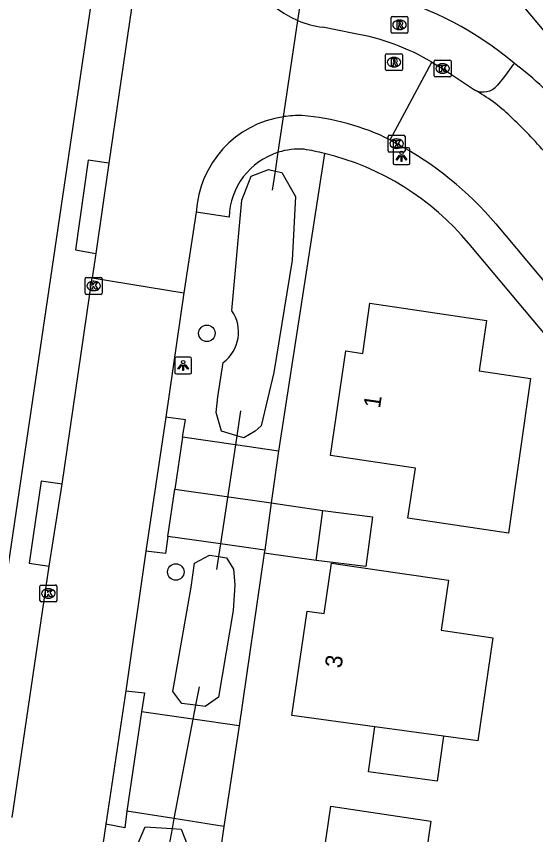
# Model space of a CAD drawing. Extents: x 164150 to 165261, y 382513 to 383432.
# Drawn here: x 164667.2 to 164697.92, y 383094.82 to 383143.23 of the extents above; entities that cross this region are included whole.
import ezdxf

# ---------------------------------------------------------------- set-up
doc = ezdxf.new("R2010")
doc.units = 0
for name, color, linetype in [('IMGEO_Boom', 7, 'Continuous'), ('IMGEO_Duiker', 7, 'Continuous'), ('IMGEO_Greppel_droge_sloot', 7, 'Continuous'), ('IMGEO_Groenvoorziening', 7, 'Continuous'), ('IMGEO_Kolk', 7, 'Continuous'), ('IMGEO_Lichtpunt', 7, 'Continuous'), ('IMGEO_Pand', 7, 'Continuous'), ('IMGEO_Pand_nummerreeks', 7, 'Continuous'), ('IMGEO_Rijbaan_lokaal_open', 7, 'Continuous'), ('IMGEO_Rioolput', 7, 'Continuous'), ('IMGEO_Voetpad_open', 7, 'Continuous')]:
    doc.layers.add(name, color=color, linetype=linetype)

msp = doc.modelspace()

# ---------------------------------------------------------------- linework, layer by layer
at = {"layer": 'IMGEO_Boom'}
for centre in [(164678.467, 383124.48), (164676.627, 383110.359)]:
    msp.add_circle(centre, 0.489, dxfattribs=at)
at = {"layer": 'IMGEO_Duiker'}
for points in [[(164682.359, 383132.944), (164682.528, 383134.079), (164682.693, 383135.192), (164683.006, 383137.299), (164683.852, 383142.989), (164684.274, 383145.824), (164684.646, 383148.329), (164684.685, 383148.589)], [(164680.465, 383119.904), (164680.238, 383118.413), (164680.158, 383117.886), (164679.265, 383112.022), (164679.151, 383111.27), (164679.035, 383110.511)], [(164678.002, 383103.555), (164677.798, 383102.481), (164677.639, 383101.645), (164676.521, 383095.769), (164676.409, 383095.178), (164676.228, 383094.227)]]:
    msp.add_lwpolyline(points, dxfattribs=at)
at = {"layer": 'IMGEO_Greppel_droge_sloot'}
for points in [[(164679.948, 383125.821), (164680.545, 383132.357), (164681.079, 383133.781), (164682.112, 383134.173), (164682.528, 383134.079), (164682.895, 383133.995), (164683.711, 383132.584)], [(164683.711, 383132.584), (164683.514, 383128.812), (164682.437, 383122.17), (164681.688, 383119.003), (164681.328, 383118.682), (164680.652, 383118.29), (164680.238, 383118.413), (164679.334, 383118.682), (164679.014, 383119.786), (164679.122, 383120.729), (164679.428, 383122.76)], [(164677.531, 383109.471), (164677.731, 383110.883), (164678.622, 383111.346), (164679.151, 383111.27), (164679.619, 383111.203), (164680.046, 383110.526), (164680.118, 383109.601), (164680.019, 383108.086), (164679.153, 383102.95), (164678.372, 383102.407), (164677.798, 383102.481), (164676.984, 383102.585), (164676.449, 383103.297), (164677.531, 383109.471)], [(164672.986, 383084.821), (164673.965, 383093.315), (164674.811, 383095.284), (164676.409, 383095.178), (164676.948, 383095.142), (164677.626, 383093.43), (164676.313, 383084.457), (164675.666, 383082.856), (164674.482, 383083.009), (164673.707, 383083.11)]]:
    msp.add_lwpolyline(points, dxfattribs=at)
msp.add_arc((164678.112, 383124.558), 2.228, 306.1933, 34.5241, dxfattribs=at)
at = {"layer": 'IMGEO_Groenvoorziening'}
for points in [[(164685.42, 383135.126), (164682.705, 383117.517)], [(164681.864, 383111.47), (164680.372, 383101.254)], [(164679.477, 383095.307), (164679.334, 383094.335)]]:
    msp.add_lwpolyline(points, dxfattribs=at)
at = {"layer": 'IMGEO_Kolk'}
for p, q in [((164691.91, 383139.721), (164691.91, 383140.573)), ((164691.985, 383140.647), (164692.837, 383140.647)), ((164692.911, 383140.573), (164692.911, 383139.721)), ((164692.398, 383140.427), (164692.423, 383140.427)), ((164692.837, 383139.647), (164691.985, 383139.647)), ((164692.421, 383139.867), (164692.396, 383139.867)), ((164689.263, 383136.204), (164690.115, 383136.204)), ((164689.188, 383135.278), (164689.188, 383136.13)), ((164689.676, 383135.984), (164689.701, 383135.984)), ((164690.189, 383136.13), (164690.189, 383135.278)), ((164689.699, 383135.424), (164689.674, 383135.424)), ((164690.115, 383135.204), (164689.263, 383135.204)), ((164671.267, 383126.859), (164671.267, 383127.711)), ((164671.342, 383127.785), (164672.194, 383127.785)), ((164671.755, 383127.565), (164671.78, 383127.565)), ((164672.268, 383127.711), (164672.268, 383126.859)), ((164671.778, 383127.005), (164671.753, 383127.005)), ((164672.194, 383126.785), (164671.342, 383126.785)), ((164668.669, 383109.589), (164669.521, 383109.589)), ((164668.594, 383108.663), (164668.594, 383109.515)), ((164669.082, 383109.369), (164669.107, 383109.369)), ((164669.595, 383109.515), (164669.595, 383108.663)), ((164669.521, 383108.589), (164668.669, 383108.589)), ((164669.105, 383108.809), (164669.08, 383108.809))]:
    msp.add_line(p, q, dxfattribs=at)
for points in [[(164691.91, 383139.721), (164691.91, 383140.573)], [(164691.985, 383140.647), (164692.837, 383140.647)], [(164692.911, 383140.573), (164692.911, 383139.721)], [(164692.231, 383140.347), (164692.354, 383140.347), (164692.354, 383140.196), (164692.484, 383140.347), (164692.648, 383140.347), (164692.502, 383140.196), (164692.655, 383139.947), (164692.503, 383139.947), (164692.418, 383140.111), (164692.354, 383140.044), (164692.354, 383139.947), (164692.231, 383139.947), (164692.231, 383140.347)], [(164692.837, 383139.647), (164691.985, 383139.647)], [(164689.263, 383136.204), (164690.115, 383136.204)], [(164689.188, 383135.278), (164689.188, 383136.13)], [(164689.509, 383135.904), (164689.632, 383135.904), (164689.632, 383135.753), (164689.762, 383135.904), (164689.926, 383135.904), (164689.78, 383135.753), (164689.933, 383135.504), (164689.781, 383135.504), (164689.696, 383135.668), (164689.632, 383135.601), (164689.632, 383135.504), (164689.509, 383135.504), (164689.509, 383135.904)], [(164690.189, 383136.13), (164690.189, 383135.278)], [(164690.115, 383135.204), (164689.263, 383135.204)], [(164671.267, 383126.859), (164671.267, 383127.711)], [(164671.342, 383127.785), (164672.194, 383127.785)], [(164671.588, 383127.485), (164671.711, 383127.485), (164671.711, 383127.334), (164671.841, 383127.485), (164672.005, 383127.485), (164671.859, 383127.334), (164672.012, 383127.085), (164671.86, 383127.085), (164671.775, 383127.249), (164671.711, 383127.182), (164671.711, 383127.085), (164671.588, 383127.085), (164671.588, 383127.485)], [(164672.268, 383127.711), (164672.268, 383126.859)], [(164672.194, 383126.785), (164671.342, 383126.785)], [(164668.669, 383109.589), (164669.521, 383109.589)], [(164668.594, 383108.663), (164668.594, 383109.515)], [(164668.915, 383109.289), (164669.038, 383109.289), (164669.038, 383109.138), (164669.168, 383109.289), (164669.332, 383109.289), (164669.186, 383109.138), (164669.339, 383108.889), (164669.187, 383108.889), (164669.102, 383109.053), (164669.038, 383108.986), (164669.038, 383108.889), (164668.915, 383108.889), (164668.915, 383109.289)], [(164669.595, 383109.515), (164669.595, 383108.663)], [(164669.521, 383108.589), (164668.669, 383108.589)]]:
    msp.add_lwpolyline(points, dxfattribs=at)
for centre, start, end in [((164691.987, 383140.571), 91.552, 178.448), ((164691.987, 383140.571), 91.552, 178.448), ((164692.835, 383140.571), 1.552, 88.448), ((164692.835, 383140.571), 1.552, 88.448), ((164691.987, 383139.723), 181.552, 268.448), ((164691.987, 383139.723), 181.552, 268.448), ((164692.835, 383139.723), 271.552, 358.448), ((164692.835, 383139.723), 271.552, 358.448), ((164689.265, 383136.128), 91.552, 178.448), ((164689.265, 383136.128), 91.552, 178.448), ((164690.113, 383136.128), 1.552, 88.448), ((164690.113, 383136.128), 1.552, 88.448), ((164689.265, 383135.28), 181.552, 268.448), ((164689.265, 383135.28), 181.552, 268.448), ((164690.113, 383135.28), 271.552, 358.448), ((164690.113, 383135.28), 271.552, 358.448), ((164671.344, 383127.709), 91.552, 178.448), ((164671.344, 383127.709), 91.552, 178.448), ((164672.192, 383127.709), 1.552, 88.448), ((164672.192, 383127.709), 1.552, 88.448), ((164671.344, 383126.861), 181.552, 268.448), ((164671.344, 383126.861), 181.552, 268.448), ((164672.192, 383126.861), 271.552, 358.448), ((164672.192, 383126.861), 271.552, 358.448), ((164668.671, 383109.513), 91.552, 178.448), ((164668.671, 383109.513), 91.552, 178.448), ((164669.519, 383109.513), 1.552, 88.448), ((164669.519, 383109.513), 1.552, 88.448), ((164668.671, 383108.665), 181.552, 268.448), ((164668.671, 383108.665), 181.552, 268.448), ((164669.519, 383108.665), 271.552, 358.448), ((164669.519, 383108.665), 271.552, 358.448)]:
    msp.add_arc(centre, 0.0765, start, end, dxfattribs=at)
for centre, major_axis, ratio, start_param, end_param in [((164692.397, 383140.147), (-0.387, 0.002), 0.722429, 4.712389, 7.853982), ((164692.422, 383140.147), (-0.39, 0.002), 0.717154, 1.570796, 4.712389), ((164689.675, 383135.704), (-0.387, 0.002), 0.722429, 4.712389, 7.853982), ((164689.7, 383135.704), (-0.39, 0.002), 0.717154, 1.570796, 4.712389), ((164671.754, 383127.285), (-0.387, 0.002), 0.722429, 4.712389, 7.853982), ((164671.779, 383127.285), (-0.39, 0.002), 0.717154, 1.570796, 4.712389), ((164669.081, 383109.089), (-0.387, 0.002), 0.722429, 4.712389, 7.853982), ((164669.106, 383109.089), (-0.39, 0.002), 0.717154, 1.570796, 4.712389)]:
    msp.add_ellipse(centre, major_axis=major_axis, ratio=ratio, start_param=start_param, end_param=end_param, dxfattribs=at)
at = {"layer": 'IMGEO_Lichtpunt'}
for p, q in [((164689.483, 383135.361), (164689.483, 383134.554)), ((164689.483, 383135.361), (164689.483, 383134.554)), ((164690.385, 383135.456), (164689.577, 383135.456)), ((164690.385, 383135.456), (164689.577, 383135.456)), ((164690.479, 383134.554), (164690.479, 383135.361)), ((164690.479, 383134.554), (164690.479, 383135.361)), ((164689.577, 383134.46), (164690.385, 383134.46)), ((164689.577, 383134.46), (164690.385, 383134.46)), ((164676.567, 383122.979), (164676.567, 383122.172)), ((164676.567, 383122.979), (164676.567, 383122.172)), ((164677.469, 383123.074), (164676.661, 383123.074)), ((164677.469, 383123.074), (164676.661, 383123.074)), ((164677.563, 383122.172), (164677.563, 383122.979)), ((164677.563, 383122.172), (164677.563, 383122.979)), ((164676.661, 383122.078), (164677.469, 383122.078)), ((164676.661, 383122.078), (164677.469, 383122.078))]:
    msp.add_line(p, q, dxfattribs=at)
for points in [[(164689.857, 383135.025), (164689.896, 383134.997), (164689.708, 383134.735), (164689.67, 383134.762), (164689.857, 383135.025)], [(164689.959, 383134.977), (164690.006, 383134.977), (164690.006, 383134.655), (164689.959, 383134.655), (164689.959, 383134.977)], [(164690.069, 383134.997), (164690.107, 383135.024), (164690.294, 383134.762), (164690.255, 383134.734), (164690.069, 383134.997)], [(164676.941, 383122.643), (164676.98, 383122.615), (164676.792, 383122.353), (164676.754, 383122.38), (164676.941, 383122.643)], [(164677.153, 383122.615), (164677.191, 383122.642), (164677.378, 383122.38), (164677.339, 383122.352), (164677.153, 383122.615)], [(164677.043, 383122.595), (164677.09, 383122.595), (164677.09, 383122.273), (164677.043, 383122.273), (164677.043, 383122.595)]]:
    msp.add_lwpolyline(points, dxfattribs=at)
for centre in [(164689.982, 383135.159), (164677.066, 383122.777)]:
    msp.add_circle(centre, 0.0994, dxfattribs=at)
for centre, start, end in [((164689.577, 383135.361), 90, 180), ((164689.577, 383135.361), 90, 180), ((164690.385, 383135.361), 0, 90), ((164690.385, 383135.361), 0, 90), ((164689.577, 383134.554), 180, 270), ((164689.577, 383134.554), 180, 270), ((164690.385, 383134.554), 270, 0), ((164690.385, 383134.554), 270, 360), ((164676.661, 383122.979), 90, 180), ((164676.661, 383122.979), 90, 180), ((164677.469, 383122.979), 0, 90), ((164677.469, 383122.979), 0, 90), ((164676.661, 383122.172), 180, 270), ((164676.661, 383122.172), 180, 270), ((164677.469, 383122.172), 270, 0), ((164677.469, 383122.172), 270, 360)]:
    msp.add_arc(centre, 0.0946, start, end, dxfattribs=at)
at = {"layer": 'IMGEO_Pand'}
for points in [[(164695.223, 383146.183), (164698.886, 383141.788), (164700.592, 383143.214), (164702.499, 383140.933), (164709.288, 383146.608), (164703.728, 383153.266)], [(164696.304, 383112.656), (164690.359, 383113.537), (164690.799, 383116.508), (164685.777, 383117.252), (164686.683, 383123.435), (164687.684, 383123.28), (164688.111, 383126.26), (164695.018, 383125.233), (164694.576, 383122.259), (164697.618, 383121.807), (164696.304, 383112.656)], [(164685.334, 383113.998), (164688.257, 383113.615), (164687.868, 383110.687), (164684.941, 383111.045)], [(164684.941, 383111.045), (164685.334, 383113.998)], [(164688.395, 383101.199), (164683.491, 383101.872), (164684.404, 383108.045), (164685.4, 383107.912), (164685.832, 383110.885), (164689.611, 383110.336), (164692.759, 383109.878), (164692.328, 383106.91), (164695.381, 383106.466), (164694.494, 383100.363), (164692.457, 383100.642)], [(164692.457, 383100.642), (164692.092, 383097.977), (164688.03, 383098.534), (164688.395, 383101.199)], [(164692.457, 383100.642), (164688.395, 383101.199)], [(164681.443, 383088.028), (164681.531, 383088.632), (164680.878, 383088.728), (164681.278, 383091.454), (164681.931, 383091.358), (164682.314, 383093.967), (164685.361, 383093.531), (164685.804, 383096.496), (164691.724, 383095.61), (164691.218, 383092.228), (164690.728, 383092.301), (164689.907, 383086.771)]]:
    msp.add_lwpolyline(points, dxfattribs=at)
at = {"layer": 'IMGEO_Rijbaan_lokaal_open'}
for points in [[(164675.111, 383151.432), (164675.108, 383151.287), (164672.668, 383134.547)], [(164687.154, 383142.219), (164685.328, 383142.586)], [(164689.308, 383135.927), (164691.776, 383140.523)], [(164691.776, 383140.523), (164692.411, 383140.147), (164694.29, 383138.89)], [(164689.308, 383135.927), (164689.689, 383135.704)], [(164672.668, 383134.547), (164671.889, 383129.204)], [(164677.839, 383131.639), (164677.103, 383126.885)], [(164695.558, 383130.959), (164698.713, 383127.191), (164713.053, 383110.049), (164722.921, 383098.245), (164733.429, 383085.658), (164742.049, 383075.319), (164755.138, 383059.563), (164759.226, 383054.634)], [(164671.889, 383129.204), (164671.68, 383127.772)], [(164669.899, 383115.549), (164671.68, 383127.772)], [(164671.68, 383127.772), (164677.103, 383126.885)], [(164677.103, 383126.885), (164676.045, 383119.511)], [(164676.045, 383119.511), (164674.86, 383111.597)], [(164669.137, 383110.698), (164669.899, 383115.549)], [(164674.86, 383111.597), (164673.679, 383103.33)], [(164666.957, 383095.84), (164669.137, 383110.698)], [(164673.679, 383103.33), (164672.483, 383095.429)], [(164672.483, 383095.429), (164670.732, 383083.53)]]:
    msp.add_lwpolyline(points, dxfattribs=at)
for centre, radius, start, end in [((164686.08, 383148.243), 5.707, 173.1633, 247.0188), ((164686.089, 383148.279), 5.744, 247.0742, 262.3827), ((164684.947, 383129.058), 13.345, 59.2202, 80.4795), ((164688.865, 383129.279), 11.037, 46.8224, 60.5579), ((164683.9, 383131.294), 6.071, 98.4693, 176.7449), ((164683.904, 383131.231), 6.135, 88.1717, 98.42), ((164682.978, 383123.122), 14.285, 63.6955, 85.4947), ((164670.416, 383110.24), 37.547, 41.4812, 46.1719), ((164680.217, 383117.986), 20.091, 40.2192, 61.8708)]:
    msp.add_arc(centre, radius, start, end, dxfattribs=at)
at = {"layer": 'IMGEO_Rioolput'}
for p, q in [((164689.362, 383142.307), (164689.362, 383143.159)), ((164689.437, 383143.233), (164690.289, 383143.233)), ((164689.85, 383143.013), (164689.875, 383143.013)), ((164690.363, 383143.159), (164690.363, 383142.307)), ((164690.289, 383142.233), (164689.437, 383142.233)), ((164689.873, 383142.453), (164689.848, 383142.453)), ((164689.115, 383141.025), (164689.967, 383141.025)), ((164689.04, 383140.099), (164689.04, 383140.951)), ((164689.528, 383140.805), (164689.553, 383140.805)), ((164690.041, 383140.951), (164690.041, 383140.099)), ((164689.551, 383140.245), (164689.526, 383140.245)), ((164689.967, 383140.025), (164689.115, 383140.025))]:
    msp.add_line(p, q, dxfattribs=at)
for points in [[(164689.362, 383142.307), (164689.362, 383143.159)], [(164689.437, 383143.233), (164690.289, 383143.233)], [(164690.363, 383143.159), (164690.363, 383142.307)], [(164689.951, 383142.931), (164689.699, 383142.933), (164689.699, 383142.533)], [(164689.699, 383142.533), (164689.823, 383142.533), (164689.823, 383142.695), (164689.834, 383142.695)], [(164689.877, 383142.852), (164689.823, 383142.852), (164689.823, 383142.771)], [(164689.823, 383142.771), (164689.875, 383142.771)], [(164689.881, 383142.666), (164689.952, 383142.533), (164690.092, 383142.533), (164690.027, 383142.659)], [(164690.289, 383142.233), (164689.437, 383142.233)], [(164689.115, 383141.025), (164689.967, 383141.025)], [(164689.04, 383140.099), (164689.04, 383140.951)], [(164689.629, 383140.723), (164689.377, 383140.725), (164689.377, 383140.325)], [(164689.555, 383140.644), (164689.501, 383140.644), (164689.501, 383140.563)], [(164689.501, 383140.563), (164689.553, 383140.563)], [(164690.041, 383140.951), (164690.041, 383140.099)], [(164689.377, 383140.325), (164689.501, 383140.325), (164689.501, 383140.487), (164689.512, 383140.487)], [(164689.559, 383140.458), (164689.63, 383140.325), (164689.77, 383140.325), (164689.705, 383140.451)], [(164689.967, 383140.025), (164689.115, 383140.025)]]:
    msp.add_lwpolyline(points, dxfattribs=at)
for centre, radius, start, end in [((164689.439, 383143.157), 0.0765, 91.552, 178.448), ((164689.439, 383143.157), 0.0765, 91.552, 178.448), ((164690.287, 383143.157), 0.0765, 1.552, 88.448), ((164690.287, 383143.157), 0.0765, 1.552, 88.448), ((164689.833, 383142.642), 0.0533, 26.0293, 88.6989), ((164689.859, 383142.96), 0.19, 274.7715, 282.9687), ((164689.883, 383142.756), 0.0964, 77.0061, 93.1865), ((164689.897, 383142.813), 0.0378, 276.6634, 79.6772), ((164689.95, 383142.821), 0.109, 350.3612, 89.416), ((164689.948, 383142.821), 0.112, 277.5842, 350.9817), ((164689.932, 383142.606), 0.108, 29.5134, 73.7905), ((164689.439, 383142.309), 0.0765, 181.552, 268.448), ((164689.439, 383142.309), 0.0765, 181.552, 268.448), ((164690.287, 383142.309), 0.0765, 271.552, 358.448), ((164690.287, 383142.309), 0.0765, 271.552, 358.448), ((164689.117, 383140.949), 0.0765, 91.552, 178.448), ((164689.117, 383140.949), 0.0765, 91.552, 178.448), ((164689.965, 383140.949), 0.0765, 1.552, 88.448), ((164689.965, 383140.949), 0.0765, 1.552, 88.448), ((164689.537, 383140.752), 0.19, 274.7715, 282.9687), ((164689.561, 383140.548), 0.0964, 77.0061, 93.1865), ((164689.575, 383140.605), 0.0378, 276.6634, 79.6772), ((164689.628, 383140.613), 0.109, 350.3612, 89.416), ((164689.626, 383140.613), 0.112, 277.5842, 350.9817), ((164689.117, 383140.101), 0.0765, 181.552, 268.448), ((164689.117, 383140.101), 0.0765, 181.552, 268.448), ((164689.511, 383140.434), 0.0533, 26.0293, 88.6989), ((164689.61, 383140.398), 0.108, 29.5134, 73.7905), ((164689.965, 383140.101), 0.0765, 271.552, 358.448), ((164689.965, 383140.101), 0.0765, 271.552, 358.448)]:
    msp.add_arc(centre, radius, start, end, dxfattribs=at)
for centre, major_axis, ratio, start_param, end_param in [((164689.849, 383142.733), (-0.387, 0.002), 0.722429, 4.712389, 7.853982), ((164689.874, 383142.733), (-0.39, 0.002), 0.717154, 1.570796, 4.712389), ((164689.527, 383140.525), (-0.387, 0.002), 0.722429, 4.712389, 7.853982), ((164689.552, 383140.525), (-0.39, 0.002), 0.717154, 1.570796, 4.712389)]:
    msp.add_ellipse(centre, major_axis=major_axis, ratio=ratio, start_param=start_param, end_param=end_param, dxfattribs=at)
at = {"layer": 'IMGEO_Voetpad_open'}
for points in [[(164653.403, 383020.558), (164672.613, 383150.649)], [(164696.647, 383140.459), (164696.079, 383139.675), (164695.664, 383139.161)], [(164672.668, 383134.547), (164671.449, 383134.735), (164670.698, 383129.426), (164671.889, 383129.204)], [(164679.779, 383131.351), (164677.839, 383131.639)], [(164757.629, 383053.516), (164711.831, 383108.452), (164704.347, 383117.418), (164693.959, 383129.801)], [(164677.033, 383118.339), (164677.208, 383119.355), (164676.045, 383119.511)], [(164677.033, 383118.339), (164676.571, 383115.268)], [(164682.705, 383117.517), (164680.158, 383117.886), (164677.033, 383118.339)], [(164682.705, 383117.517), (164682.279, 383114.453)], [(164669.899, 383115.549), (164668.674, 383115.736), (164667.959, 383110.888), (164669.137, 383110.698)], [(164676.149, 383112.464), (164676.571, 383115.268)], [(164676.571, 383115.268), (164682.279, 383114.453)], [(164682.279, 383114.453), (164681.89, 383111.65)], [(164682.279, 383114.453), (164685.334, 383113.998)], [(164676.149, 383112.464), (164676.023, 383111.451), (164674.86, 383111.597)], [(164681.89, 383111.65), (164679.265, 383112.022), (164676.149, 383112.464)], [(164681.89, 383111.65), (164681.864, 383111.47)], [(164684.941, 383111.045), (164681.864, 383111.47)], [(164673.679, 383103.33), (164674.787, 383103.219), (164674.604, 383102.079)], [(164674.604, 383102.079), (164673.742, 383096.204)], [(164680.372, 383101.254), (164677.639, 383101.645), (164674.604, 383102.079)], [(164680.372, 383101.254), (164679.477, 383095.307)], [(164673.742, 383096.204), (164673.609, 383095.219), (164672.483, 383095.429)], [(164679.477, 383095.307), (164676.521, 383095.769), (164673.742, 383096.204)]]:
    msp.add_lwpolyline(points, dxfattribs=at)
for centre, radius, start, end in [((164683.507, 383124.825), 20.423, 49.9527, 74.405), ((164686.367, 383126.62), 17.239, 38.4289, 53.3939), ((164694.812, 383139.861), 1.102, 241.7253, 320.5896), ((164683.932, 383131.216), 4.164, 86.1159, 107.3082), ((164681.588, 383119.354), 16.23, 76.3439, 80.6893), ((164683.931, 383131.227), 4.154, 107.3391, 178.2889), ((164681.621, 383119.524), 16.057, 39.7906, 76.3133)]:
    msp.add_arc(centre, radius, start, end, dxfattribs=at)

# ---------------------------------------------------------------- texts
at = {"layer": 'IMGEO_Pand_nummerreeks'}
for s, rotation, p in [('1', 81.6637, (164688.708, 383120.011)), ('3', 81.5892, (164686.427, 383104.632))]:
    msp.add_text(s, height=1, rotation=rotation, dxfattribs=at).set_placement(p)

doc.saveas('drawing.dxf')
